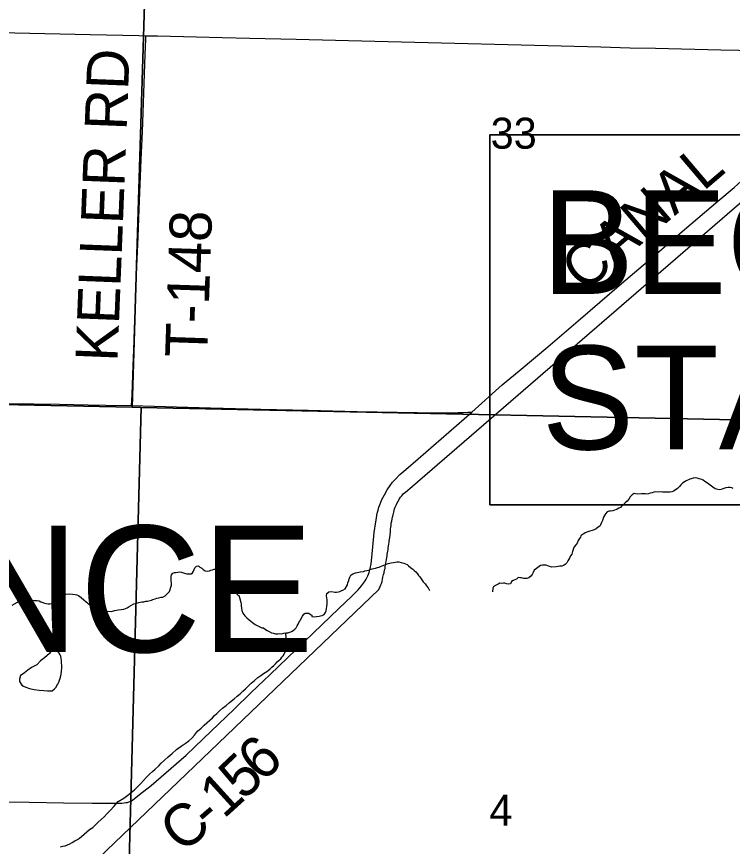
# Model space of a CAD drawing. Extents: x 0 to 34, y 0 to 22.
# Drawn here: x 3.218 to 4.185, y 15.859 to 16.98 of the extents above; entities that cross this region are included whole.
import ezdxf

# ---------------------------------------------------------------- set-up
doc = ezdxf.new("R2010")
doc.units = 0
for name, color, linetype in [('GM_X_County_Road', 7, 'Continuous'), ('GM_X_County_Road_Text', 7, 'Continuous'), ('GM_X_Minor_Lake', 7, 'Continuous'), ('GM_X_Minor_River', 7, 'Continuous'), ('GM_X_Section', 7, 'Continuous'), ('GM_X_Section_Text', 7, 'Continuous'), ('GM_X_Township_Road', 7, 'Continuous'), ('GM_X_Township_Road_Text', 7, 'Continuous'), ('GM_X_Township_Text', 7, 'Continuous'), ('SH_Masking', 7, 'Continuous'), ('SH_Text', 7, 'Continuous')]:
    doc.layers.add(name, color=color, linetype=linetype)

msp = doc.modelspace()

# ---------------------------------------------------------------- linework, layer by layer
at = {"layer": 'GM_X_County_Road'}
for points in [[(3.8332, 16.446), (3.8742, 16.4827), (3.8997, 16.5037), (3.9358, 16.5341), (3.9769, 16.5693), (4.0355, 16.6194), (4.0761, 16.6543), (4.1205, 16.6923), (4.1653, 16.7308), (4.1873, 16.7493), (4.1974, 16.7581), (4.2111, 16.7698), (4.2143, 16.7725)], [(3.2066, 16.4577), (3.2762, 16.4566), (3.3147, 16.4555), (3.3384, 16.4552), (3.3733, 16.4546)], [(3.3733, 16.4546), (3.4801, 16.4517), (3.5478, 16.4499), (3.6118, 16.4483), (3.6783, 16.4466), (3.759, 16.4452), (3.788, 16.445), (3.8009, 16.445), (3.8144, 16.4452), (3.8218, 16.4455), (3.8275, 16.4457), (3.8332, 16.446)], [(3.3746, 15.922), (3.3843, 15.9294), (3.3999, 15.9416), (3.4472, 15.9828), (3.4702, 16.0046), (3.5119, 16.0446), (3.5351, 16.0671), (3.5607, 16.0916), (3.5956, 16.1253), (3.6536, 16.1807), (3.6711, 16.1975), (3.6794, 16.2058), (3.6842, 16.2114), (3.6879, 16.2165), (3.6903, 16.2205), (3.6925, 16.2249), (3.6942, 16.2294), (3.6959, 16.2349), (3.6969, 16.241), (3.6978, 16.2494), (3.7012, 16.2834), (3.7033, 16.2976), (3.7041, 16.3027), (3.7048, 16.3069), (3.7057, 16.3106), (3.7066, 16.3137), (3.7076, 16.3174), (3.7089, 16.3209), (3.7116, 16.3277), (3.715, 16.3344), (3.7188, 16.3409), (3.7226, 16.3466), (3.726, 16.3511), (3.7298, 16.3554), (3.736, 16.3615), (3.7439, 16.3686), (3.7606, 16.3826), (3.8332, 16.446)]]:
    msp.add_lwpolyline(points, dxfattribs=at)
at = {"layer": 'GM_X_Minor_Lake'}
for points in [[(3.2669, 16.128), (3.2665, 16.1265), (3.2625, 16.1198), (3.2558, 16.1139), (3.2504, 16.1099), (3.2453, 16.1048), (3.2383, 16.1008), (3.2332, 16.0972), (3.2289, 16.0939), (3.2254, 16.0917), (3.2235, 16.0903), (3.2218, 16.0854), (3.2221, 16.0823), (3.2253, 16.0773), (3.2272, 16.0757), (3.2306, 16.0745), (3.2355, 16.0728), (3.2419, 16.0714), (3.2487, 16.0704), (3.2548, 16.0698), (3.2597, 16.0693)], [(3.2669, 16.128), (3.2665, 16.1265), (3.2625, 16.1198), (3.2558, 16.1139), (3.2504, 16.1099), (3.2453, 16.1048), (3.2383, 16.1008), (3.2332, 16.0972), (3.2289, 16.0939), (3.2254, 16.0917), (3.2235, 16.0903), (3.2218, 16.0854), (3.2221, 16.0823), (3.2253, 16.0773), (3.2272, 16.0757), (3.2306, 16.0745), (3.2355, 16.0728), (3.2419, 16.0714), (3.2487, 16.0704), (3.2548, 16.0698), (3.2597, 16.0693), (3.2639, 16.0695), (3.2662, 16.0695), (3.2694, 16.0724), (3.2717, 16.0746), (3.2725, 16.0765), (3.2737, 16.0787), (3.275, 16.081), (3.2758, 16.084), (3.2775, 16.0881), (3.2784, 16.0919), (3.2789, 16.0961), (3.279, 16.1006), (3.2791, 16.104), (3.2788, 16.1067), (3.2789, 16.1086), (3.2786, 16.1105), (3.2783, 16.1132), (3.278, 16.1163), (3.2769, 16.1182), (3.2755, 16.1205), (3.2669, 16.128)], [(3.2597, 16.0693), (3.2639, 16.0695), (3.2662, 16.0695), (3.2694, 16.0724), (3.2717, 16.0746), (3.2725, 16.0765), (3.2737, 16.0787), (3.275, 16.081), (3.2758, 16.084), (3.2775, 16.0881), (3.2784, 16.0919), (3.2789, 16.0961), (3.279, 16.1006), (3.2791, 16.104), (3.2788, 16.1067), (3.2789, 16.1086), (3.2786, 16.1105), (3.2783, 16.1132), (3.278, 16.1163), (3.2769, 16.1182), (3.2755, 16.1205), (3.2669, 16.128)]]:
    msp.add_lwpolyline(points, dxfattribs=at)
at = {"layer": 'GM_X_Minor_River'}
msp.add_line((2.1, 14.667), (3.7075, 16.2064), dxfattribs=at)
for points in [[(3.743, 16.3375), (5.6291, 17.9671)], [(4.186, 16.3427), (4.1842, 16.3438), (4.1823, 16.3443), (4.1792, 16.344), (4.1762, 16.3437), (4.1724, 16.3422), (4.1701, 16.3412), (4.1682, 16.3408), (4.1655, 16.3413), (4.1636, 16.3417), (4.1617, 16.3425), (4.1587, 16.3445), (4.1569, 16.3457), (4.155, 16.3472), (4.1531, 16.3484), (4.1502, 16.3508), (4.1479, 16.352), (4.1457, 16.3539), (4.1438, 16.3547), (4.1404, 16.356), (4.1374, 16.3568), (4.1348, 16.3573), (4.1321, 16.3569), (4.1294, 16.3559), (4.1275, 16.3552), (4.1256, 16.3544), (4.1236, 16.3534), (4.1217, 16.3526), (4.1198, 16.3515), (4.1175, 16.3501), (4.1155, 16.3475), (4.1136, 16.3456), (4.1108, 16.3427), (4.1077, 16.3405), (4.1054, 16.339), (4.1035, 16.3383), (4.1005, 16.3376), (4.0986, 16.3377), (4.0951, 16.3377), (4.0929, 16.3378), (4.0906, 16.3379), (4.0876, 16.3383), (4.0841, 16.338), (4.0811, 16.3381), (4.0788, 16.3378), (4.0769, 16.3371), (4.0738, 16.3364), (4.0719, 16.3357), (4.0696, 16.3353), (4.0674, 16.3354), (4.0655, 16.3355), (4.0624, 16.3355), (4.0567, 16.3353), (4.0544, 16.3357), (4.0525, 16.3358), (4.0495, 16.334), (4.0471, 16.3314), (4.0451, 16.3284), (4.0428, 16.3258), (4.0401, 16.3236), (4.0373, 16.3202), (4.0354, 16.3191), (4.0339, 16.3173), (4.0319, 16.3162), (4.0296, 16.3147), (4.0277, 16.314), (4.0258, 16.3133), (4.0235, 16.3126), (4.0204, 16.3123), (4.0185, 16.312), (4.0158, 16.3113), (4.0135, 16.3083), (4.0123, 16.3064), (4.0111, 16.3042), (4.0095, 16.2993), (4.0083, 16.2966), (4.0071, 16.2936), (4.0059, 16.2918), (4.0039, 16.2903), (4.0012, 16.2881), (3.9985, 16.287), (3.9955, 16.286), (3.9924, 16.2849), (3.9897, 16.2842), (3.9863, 16.2828), (3.9843, 16.2817), (3.9824, 16.2806), (3.9805, 16.2787), (3.9797, 16.2769), (3.9785, 16.275), (3.9769, 16.2724), (3.9753, 16.269), (3.9741, 16.2671)], [(3.7075, 16.2064), (3.7094, 16.2104), (3.7103, 16.2127), (3.7111, 16.2145), (3.7119, 16.2172), (3.7123, 16.2198), (3.7128, 16.2228), (3.7136, 16.2266), (3.7148, 16.2289), (3.7153, 16.233), (3.7158, 16.2349), (3.7162, 16.2372), (3.7166, 16.2391), (3.7171, 16.2417), (3.7175, 16.2444), (3.7179, 16.2466), (3.7184, 16.2497), (3.7188, 16.2519), (3.7189, 16.2538), (3.7193, 16.2557), (3.7197, 16.258), (3.7202, 16.2599), (3.7202, 16.2625), (3.7207, 16.2648), (3.7211, 16.2678), (3.7216, 16.2697), (3.7216, 16.2716), (3.722, 16.2739), (3.7225, 16.2769), (3.7226, 16.2792), (3.7226, 16.2811), (3.723, 16.2834), (3.7231, 16.286), (3.7232, 16.2883), (3.7236, 16.2902), (3.724, 16.2932), (3.7241, 16.2959), (3.7249, 16.2985), (3.7254, 16.3019), (3.7258, 16.3042), (3.7267, 16.3072), (3.7275, 16.3106), (3.7283, 16.3132), (3.7288, 16.3151), (3.7296, 16.3174), (3.7312, 16.3211), (3.7324, 16.3234), (3.7336, 16.3252), (3.7344, 16.3275), (3.7368, 16.3309), (3.7383, 16.3327), (3.7407, 16.3361), (3.743, 16.3375)], [(3.9741, 16.2671), (3.9714, 16.2638), (3.9705, 16.2615), (3.9693, 16.2577), (3.9681, 16.254), (3.9665, 16.2517), (3.9653, 16.2495), (3.9641, 16.2472), (3.9629, 16.245), (3.9613, 16.2424), (3.959, 16.2402), (3.9567, 16.2387), (3.9548, 16.238), (3.9521, 16.2377), (3.9498, 16.2374), (3.9471, 16.237), (3.941, 16.2364), (3.938, 16.2373), (3.9358, 16.2385), (3.9335, 16.2393), (3.9309, 16.2394), (3.9286, 16.2394), (3.9259, 16.2387), (3.924, 16.2372), (3.9205, 16.2347), (3.9174, 16.2325), (3.9158, 16.2295), (3.9146, 16.2268), (3.9126, 16.2242), (3.9103, 16.222), (3.9072, 16.221), (3.9053, 16.221), (3.9034, 16.2214), (3.9004, 16.2219), (3.8981, 16.2223), (3.8959, 16.2224), (3.8935, 16.2205), (3.8889, 16.2184), (3.8866, 16.2173), (3.8854, 16.2139), (3.8831, 16.2136), (3.8801, 16.214), (3.8778, 16.2149), (3.8759, 16.2149), (3.8736, 16.2146), (3.871, 16.2147), (3.8687, 16.2136), (3.8652, 16.2118), (3.8625, 16.2099), (3.8613, 16.2081), (3.8612, 16.2032)], [(3.4274, 16.2121), (3.4267, 16.2206), (3.4267, 16.2217), (3.4268, 16.224), (3.4272, 16.2263), (3.4292, 16.2285), (3.4315, 16.2292), (3.4334, 16.2295), (3.4361, 16.2299), (3.4387, 16.2302), (3.441, 16.2297), (3.4436, 16.2289), (3.4463, 16.2281), (3.4482, 16.2277), (3.4512, 16.2276), (3.4538, 16.2275), (3.4558, 16.229), (3.457, 16.2312), (3.4578, 16.2335), (3.459, 16.2357), (3.4609, 16.238), (3.4636, 16.2383), (3.4658, 16.2367), (3.4681, 16.2351), (3.4703, 16.2335), (3.4729, 16.2316), (3.476, 16.2311), (3.4786, 16.2314), (3.4806, 16.2325), (3.4828, 16.2329), (3.4851, 16.2336), (3.4874, 16.2339), (3.4897, 16.2346), (3.4916, 16.2345), (3.4942, 16.2329), (3.4949, 16.2306), (3.4949, 16.2284), (3.4941, 16.2265), (3.4932, 16.2223), (3.4928, 16.2204), (3.4931, 16.2178), (3.495, 16.2158), (3.4972, 16.215), (3.4998, 16.2138), (3.5017, 16.2126), (3.504, 16.2118), (3.51, 16.2107)], [(3.6619, 16.2074), (3.6651, 16.2127), (3.6655, 16.2153), (3.6667, 16.2187), (3.6675, 16.2206), (3.6684, 16.2232), (3.6696, 16.2255), (3.6723, 16.2277), (3.6757, 16.2287), (3.678, 16.2294), (3.6803, 16.2297), (3.6822, 16.2301), (3.6868, 16.2307), (3.6887, 16.2314), (3.691, 16.2321), (3.6937, 16.2324), (3.6956, 16.2332), (3.6986, 16.2342), (3.7009, 16.2349), (3.7028, 16.2353), (3.7055, 16.2359), (3.7078, 16.2366), (3.7097, 16.2374), (3.712, 16.2384), (3.7155, 16.2395), (3.7178, 16.2406), (3.7201, 16.2413), (3.7224, 16.242), (3.7243, 16.2423), (3.7273, 16.243), (3.7296, 16.2433), (3.7323, 16.2436), (3.7346, 16.2436), (3.7376, 16.2427), (3.741, 16.2419), (3.7436, 16.2411), (3.7459, 16.2399), (3.7477, 16.2383), (3.7503, 16.2359), (3.7533, 16.234), (3.7552, 16.232), (3.7574, 16.2301), (3.7596, 16.2277), (3.7611, 16.2254), (3.7626, 16.2235), (3.7673, 16.2169), (3.7699, 16.2138), (3.7718, 16.2115), (3.774, 16.2088), (3.7761, 16.2051)], [(3.2898, 16.2003), (3.2936, 16.2002), (3.297, 16.1997), (3.2993, 16.1993), (3.3016, 16.1984), (3.3034, 16.1968), (3.3053, 16.1956), (3.309, 16.1925), (3.3119, 16.1897), (3.3142, 16.1881), (3.3175, 16.1853), (3.3194, 16.1838), (3.3216, 16.1822), (3.3254, 16.1805), (3.3295, 16.1792), (3.3337, 16.178), (3.3374, 16.1771), (3.3458, 16.1768), (3.3508, 16.1778), (3.3554, 16.1788), (3.3592, 16.1794), (3.3627, 16.1797), (3.365, 16.1807), (3.3673, 16.1818), (3.37, 16.1832), (3.3731, 16.185), (3.3766, 16.1868), (3.3801, 16.1878), (3.3831, 16.1889), (3.3873, 16.1895), (3.39, 16.1898), (3.3927, 16.1905), (3.395, 16.1908), (3.3969, 16.1911), (3.4004, 16.1921), (3.4023, 16.1928), (3.4054, 16.1938), (3.4073, 16.1945), (3.4104, 16.1952), (3.4134, 16.1959), (3.4157, 16.1962), (3.4188, 16.198), (3.4204, 16.1998), (3.4224, 16.2013), (3.4244, 16.2035), (3.4274, 16.2121)], [(3.51, 16.2107), (3.5164, 16.1993), (3.5183, 16.1981), (3.5193, 16.1954), (3.521, 16.1889), (3.5213, 16.187), (3.5216, 16.1843), (3.5219, 16.1812), (3.5222, 16.1778), (3.5236, 16.1743), (3.5265, 16.1708), (3.5291, 16.1681), (3.5321, 16.1653), (3.5343, 16.1637), (3.5369, 16.1617), (3.5402, 16.1593), (3.5447, 16.1569), (3.5492, 16.1548), (3.5515, 16.1544), (3.5541, 16.1524), (3.5567, 16.1512), (3.5594, 16.1496), (3.5624, 16.1479), (3.565, 16.1475), (3.568, 16.1466), (3.5711, 16.1465), (3.573, 16.1468), (3.576, 16.1467), (3.5791, 16.1474), (3.5818, 16.1477), (3.5844, 16.148), (3.5871, 16.1486), (3.5894, 16.1497), (3.5918, 16.1512), (3.5941, 16.1526), (3.5957, 16.1545), (3.5969, 16.1575), (3.5985, 16.1597), (3.5993, 16.1616), (3.6006, 16.1634), (3.6014, 16.1653), (3.6042, 16.1705), (3.6062, 16.1731), (3.6081, 16.1742), (3.6104, 16.1745), (3.6127, 16.1744), (3.6149, 16.1728), (3.6168, 16.1716), (3.6171, 16.1697), (3.6209, 16.1696), (3.6232, 16.1699), (3.6267, 16.1705), (3.6286, 16.1709), (3.6309, 16.1712), (3.6336, 16.1726), (3.6356, 16.1752), (3.6364, 16.1775), (3.6369, 16.1805), (3.6374, 16.1835), (3.6375, 16.1866), (3.6376, 16.1896), (3.6377, 16.1926), (3.6374, 16.1949), (3.6367, 16.1976), (3.6372, 16.201), (3.6399, 16.2032), (3.6441, 16.2035), (3.6479, 16.2029), (3.6502, 16.2029), (3.6529, 16.2032), (3.6548, 16.2035), (3.6575, 16.2049), (3.6586, 16.2053), (3.6619, 16.2074)], [(3.212, 16.1854), (3.2194, 16.1893), (3.2217, 16.1904), (3.2236, 16.1911), (3.2267, 16.1921), (3.2286, 16.1925), (3.2309, 16.192), (3.2362, 16.1918), (3.2412, 16.1917), (3.2457, 16.1915), (3.2484, 16.191), (3.2506, 16.1898), (3.2533, 16.189), (3.2559, 16.1881), (3.2582, 16.1873), (3.2608, 16.1868), (3.2631, 16.1871), (3.2658, 16.1874), (3.2689, 16.1885), (3.2708, 16.1892), (3.2731, 16.1906), (3.2763, 16.1943), (3.2787, 16.1973), (3.2803, 16.1991), (3.2845, 16.2001), (3.2898, 16.2003)], [(3.3029, 15.8704), (3.3056, 15.873), (3.3095, 15.8759), (3.3131, 15.8792), (3.3166, 15.8821), (3.3209, 15.885), (3.3244, 15.8883), (3.3283, 15.892), (3.3323, 15.8957), (3.3362, 15.8994), (3.3405, 15.9038), (3.3449, 15.9082), (3.3496, 15.9134), (3.3551, 15.92), (3.3629, 15.9244), (3.3683, 15.9284), (3.373, 15.932), (3.3773, 15.9357), (3.3813, 15.9397), (3.3856, 15.9441), (3.3896, 15.9486), (3.3935, 15.953), (3.3978, 15.9571), (3.4017, 15.9604), (3.4053, 15.9637), (3.41, 15.9681), (3.4135, 15.9718), (3.4178, 15.9758), (3.4226, 15.9802), (3.428, 15.985), (3.4343, 15.9901), (3.4402, 15.9948), (3.446, 15.9985), (3.4507, 16.0021), (3.455, 16.0058), (3.4585, 16.0095), (3.4625, 16.015), (3.4676, 16.0191), (3.4715, 16.0231), (3.4825, 16.033), (3.4853, 16.036), (3.4884, 16.0389), (3.492, 16.0426), (3.4963, 16.0463), (3.501, 16.0499), (3.5057, 16.0539), (3.5119, 16.0587), (3.5162, 16.0623), (3.5201, 16.0656), (3.5237, 16.0689), (3.5272, 16.0723), (3.5307, 16.0759), (3.535, 16.08), (3.5394, 16.0836), (3.544, 16.0873), (3.5479, 16.0902), (3.5518, 16.0927), (3.5538, 16.0942), (3.5561, 16.0956), (3.5581, 16.0971), (3.5604, 16.0993), (3.5628, 16.1015), (3.5655, 16.1037), (3.5679, 16.1059), (3.5702, 16.1085), (3.573, 16.1107), (3.5749, 16.1129), (3.5765, 16.1148), (3.5781, 16.1166), (3.5797, 16.1192), (3.5814, 16.123), (3.5818, 16.1249), (3.5823, 16.1271), (3.5827, 16.1298), (3.5828, 16.1324), (3.5833, 16.1358), (3.583, 16.1385), (3.5823, 16.1412), (3.5818, 16.1477)], [(3.2774, 15.8587), (3.2805, 15.8597), (3.2835, 15.8604), (3.2866, 15.8614), (3.2901, 15.8628), (3.2932, 15.8646), (3.2967, 15.8668), (3.3002, 15.8686), (3.3029, 15.8704)]]:
    msp.add_lwpolyline(points, dxfattribs=at)
at = {"layer": 'GM_X_Section'}
for points in [[(2.3981, 17.4793), (3.4048, 17.4531), (3.3743, 16.4525), (2.3859, 16.4729), (2.3712, 16.4736)], [(3.4048, 17.4531), (4.411, 17.4319), (4.3846, 16.4315), (3.3864, 16.4522), (3.3743, 16.4525)], [(2.3859, 16.4729), (3.3743, 16.4525), (3.3864, 16.4522), (3.3587, 15.4138), (2.3688, 15.4332)], [(3.3864, 16.4522), (4.3846, 16.4315), (4.3576, 15.3927), (3.3587, 15.4138)]]:
    msp.add_lwpolyline(points, close=True, dxfattribs=at)
at = {"layer": 'GM_X_Township_Road'}
for points in [[(2.3837, 16.9788), (2.3929, 16.9786), (2.4152, 16.9779), (2.4705, 16.9765), (2.5302, 16.9748), (2.5532, 16.9745), (2.5936, 16.9736), (2.6389, 16.9726), (2.6644, 16.9717), (2.6818, 16.9714), (2.7048, 16.971), (2.762, 16.9697), (2.8987, 16.9661), (2.995, 16.9637), (3.0739, 16.9618), (3.0963, 16.9613), (3.1199, 16.9607), (3.2156, 16.9582), (3.3175, 16.9558), (3.3616, 16.9547), (3.3834, 16.9543), (3.3926, 16.9542)], [(3.3733, 16.4546), (3.3736, 16.4616), (3.374, 16.4698), (3.3754, 16.5089), (3.3763, 16.5294), (3.3775, 16.5579), (3.3789, 16.5933), (3.3801, 16.6325), (3.3822, 16.6827), (3.3836, 16.72), (3.3863, 16.7871), (3.388, 16.8243), (3.3895, 16.8634), (3.3918, 16.9286), (3.3925, 16.9497), (3.3926, 16.9542)], [(3.3926, 16.9542), (3.3971, 16.9541), (3.4083, 16.9541), (3.4611, 16.9528), (3.4959, 16.9519), (3.5332, 16.9508), (3.5959, 16.9493), (3.7022, 16.9469), (3.7382, 16.9461), (3.7743, 16.9452), (3.9178, 16.9412), (4.0073, 16.939), (4.0464, 16.938), (4.0812, 16.9373), (4.1695, 16.9352), (4.2422, 16.9336), (4.2733, 16.9329), (4.3087, 16.9322), (4.3986, 16.9305)], [(3.1662, 15.92), (3.2352, 15.919), (3.2812, 15.9182), (3.3203, 15.9177), (3.3446, 15.9177), (3.3552, 15.9178), (3.3603, 15.918), (3.3633, 15.9183), (3.3658, 15.9185), (3.3679, 15.9189), (3.3698, 15.9195), (3.3716, 15.9202), (3.3732, 15.9211), (3.3746, 15.922)]]:
    msp.add_lwpolyline(points, dxfattribs=at)
at = {"layer": 'SH_Masking'}
msp.add_lwpolyline([(3.8575, 16.8205), (5.6021, 16.8205), (5.6021, 16.3205), (3.8575, 16.3205)], close=True, dxfattribs=at)
at = {"layer": 'SH_Text'}
msp.add_lwpolyline([(3.8575, 16.3205), (5.6021, 16.3205), (5.6021, 16.8205), (3.8575, 16.8205)], close=True, dxfattribs=at)

# ---------------------------------------------------------------- texts
at = {"layer": 'GM_X_County_Road_Text'}
for s, height, rotation, p in [('CANAL', 0.05682, 40.3875, (3.9849, 16.6065)), ('6', 0.0568, 43.8052, (3.5503, 15.9445)), ('5', 0.0568, 43.4837, (3.5247, 15.9202)), ('1', 0.0568, 42.2546, (3.4978, 15.8957)), ('C', 0.0568, 39.3401, (3.4416, 15.8488)), ('-', 0.0568, 40.7334, (3.4789, 15.8794))]:
    msp.add_text(s, height=height, rotation=rotation, dxfattribs=at).set_placement(p)
at = {"layer": 'GM_X_Section_Text'}
for s, height, p in [('33', 0.04186, (3.8585, 16.8016)), ('4', 0.0419, (3.8568, 15.8873))]:
    msp.add_text(s, height=height, rotation=0, dxfattribs=at).set_placement(p)
at = {"layer": 'GM_X_Township_Road_Text'}
for s, rotation, p in [('KELLER RD', 87.739, (3.3543, 16.5134)), ('T-148', 88.0353, (3.4754, 16.5189))]:
    msp.add_text(s, height=0.05682, rotation=rotation, dxfattribs=at).set_placement(p)
at = {"layer": 'GM_X_Township_Text'}
msp.add_text('DEFIANCE', height=0.17045, rotation=0, dxfattribs=at).set_placement((2.4671, 16.1219))
at = {"layer": 'SH_Text'}
for s, p in [('BEGIN PROJECT', (3.9275, 16.6055)), ('STA. 224+10.00', (3.9275, 16.3955))]:
    msp.add_text(s, height=0.14, dxfattribs=at).set_placement(p)

doc.saveas('drawing.dxf')
